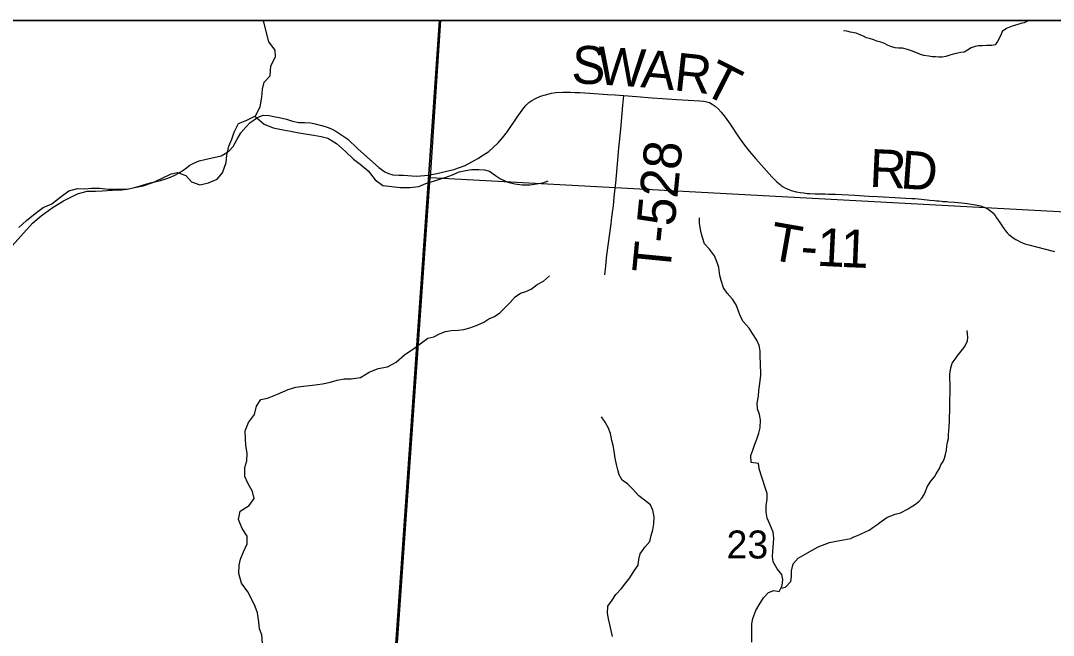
# Model space of a CAD drawing. Extents: x -8.2 to 34, y 0 to 22.
# Drawn here: x 6.05 to 7.595, y 19.98 to 20.9 of the extents above; entities that cross this region are included whole.
import ezdxf

# ---------------------------------------------------------------- set-up
doc = ezdxf.new("R2010")
doc.units = 0
for name, color, linetype in [('GM_X_Corporation', 7, 'Continuous'), ('GM_X_Minor_River', 7, 'Continuous'), ('GM_X_Section_Text', 7, 'Continuous'), ('GM_X_Township_Road', 7, 'Continuous'), ('GM_X_Township_Road_Text', 7, 'Continuous'), ('GM_X_Township_Text', 7, 'Continuous'), ('SH_Data', 7, 'Continuous')]:
    doc.layers.add(name, color=color, linetype=linetype)

msp = doc.modelspace()

# ---------------------------------------------------------------- linework, layer by layer
at = {"layer": 'GM_X_Corporation'}
msp.add_lwpolyline([(6.4774, 18.0203), (6.488, 18.1752), (6.5242, 18.7061), (6.5297, 18.7882), (6.5448, 18.981), (6.5455, 18.9878), (6.5461, 19.0017), (6.5463, 19.009), (6.5469, 19.0218), (6.548, 19.0467), (6.5487, 19.0617), (6.5495, 19.0821), (6.5503, 19.0966), (6.5514, 19.1092), (6.5523, 19.118), (6.5529, 19.1264), (6.5537, 19.1382), (6.5541, 19.1447), (6.5536, 19.1514), (6.5814, 19.5334), (6.6608, 20.6695), (6.6768, 20.9), (2.1, 20.9), (2.1, 14.1)], dxfattribs=at)
for points in [[(7.7078, 20.9), (6.6786, 20.9), (6.6629, 20.6653), (7.6877, 20.6096)], [(6.6629, 20.6653), (7.6877, 20.6096), (7.6147, 19.5864), (6.5914, 19.6487)]]:
    msp.add_lwpolyline(points, close=True, dxfattribs=at)
at = {"layer": 'GM_X_Minor_River'}
for points in [[(6.0474, 20.5902), (6.0587, 20.6008), (6.072, 20.6114), (6.0841, 20.6201), (6.097, 20.6258), (6.1106, 20.6368), (6.1223, 20.6452), (6.1352, 20.6486), (6.1458, 20.6482), (6.1564, 20.649), (6.1681, 20.649), (6.1814, 20.6479), (6.1958, 20.6475), (6.2094, 20.6479), (6.223, 20.6506), (6.2336, 20.6528), (6.248, 20.6578), (6.2609, 20.6635), (6.2753, 20.6707), (6.2851, 20.6726), (6.2972, 20.668), (6.3056, 20.6586), (6.3184, 20.6544), (6.3313, 20.6574), (6.3442, 20.6628), (6.3521, 20.6722), (6.3578, 20.6878), (6.3589, 20.6988), (6.3615, 20.7121), (6.3661, 20.7227), (6.3695, 20.7329), (6.3763, 20.7458), (6.3876, 20.7504), (6.4016, 20.7576), (6.4088, 20.7709), (6.4111, 20.7853), (6.4122, 20.7975), (6.4144, 20.8077), (6.4235, 20.8172), (6.4243, 20.8324), (6.4314, 20.846), (6.4311, 20.8559), (6.4216, 20.8684), (6.4174, 20.8836), (6.4147, 20.8961), (6.4129, 20.9)], [(7.5582, 20.9), (7.5577, 20.8997), (7.5516, 20.8967), (7.5467, 20.8955), (7.541, 20.8935), (7.5354, 20.8923), (7.5301, 20.8904), (7.5252, 20.8884), (7.5191, 20.8838), (7.5169, 20.8781), (7.5117, 20.8689), (7.5083, 20.8636), (7.5034, 20.8628), (7.4962, 20.8627), (7.489, 20.8622), (7.4837, 20.8622), (7.4784, 20.8614), (7.4727, 20.8594), (7.467, 20.8556), (7.4621, 20.8529), (7.4572, 20.8524), (7.4527, 20.8513), (7.4474, 20.8504), (7.4406, 20.8485), (7.4345, 20.8465), (7.4292, 20.8453), (7.4243, 20.8453), (7.419, 20.8456), (7.414, 20.846), (7.4091, 20.847), (7.4015, 20.8477), (7.3969, 20.8492), (7.3897, 20.8522), (7.3832, 20.8548), (7.3771, 20.857), (7.3699, 20.8588), (7.3638, 20.8588), (7.3588, 20.8591), (7.3539, 20.8606), (7.3482, 20.8628), (7.3428, 20.8658), (7.3375, 20.8677), (7.3314, 20.8695), (7.3268, 20.8714), (7.3204, 20.8732), (7.3158, 20.8743), (7.3112, 20.8769), (7.3051, 20.8791), (7.3002, 20.8814), (7.2918, 20.8828), (7.2865, 20.8843), (7.2815, 20.8846)], [(6.4008, 20.7572), (6.4145, 20.7451), (6.4282, 20.7394), (6.4429, 20.7368), (6.4539, 20.7345), (6.4638, 20.7326), (6.4789, 20.73), (6.4888, 20.7288), (6.5001, 20.7266), (6.51, 20.7239), (6.5228, 20.7163), (6.5365, 20.7042), (6.5482, 20.6928), (6.5581, 20.6852), (6.5702, 20.675), (6.5808, 20.6617), (6.5922, 20.653), (6.6055, 20.6515), (6.6183, 20.6504), (6.6327, 20.6504), (6.646, 20.6515), (6.6564, 20.6564)], [(6.6564, 20.6564), (6.6855, 20.665), (6.6965, 20.6693), (6.7064, 20.6735), (6.7162, 20.6758), (6.7246, 20.6774), (6.736, 20.6774), (6.7444, 20.6767), (6.752, 20.6745), (6.7608, 20.6681), (6.7684, 20.6632), (6.7791, 20.6583), (6.7897, 20.6557), (6.8008, 20.6542), (6.8122, 20.6543), (6.8221, 20.6555), (6.8316, 20.6574), (6.8395, 20.6601)], [(7.1443, 19.9696), (7.1441, 19.9969), (7.1456, 20.0049), (7.1505, 20.0171), (7.1554, 20.0255), (7.1618, 20.0358), (7.1694, 20.0438), (7.1773, 20.0472), (7.1853, 20.0454), (7.1898, 20.0545), (7.1909, 20.0632), (7.189, 20.0708), (7.1821, 20.0795), (7.1763, 20.0897), (7.1751, 20.0981), (7.1758, 20.1057), (7.1765, 20.1175), (7.1772, 20.1254), (7.176, 20.1342), (7.1714, 20.1463), (7.1672, 20.1554), (7.166, 20.1641), (7.1656, 20.1736), (7.1674, 20.1835), (7.167, 20.1922), (7.1639, 20.2024), (7.1608, 20.2119), (7.1577, 20.221), (7.1553, 20.2294), (7.1542, 20.2373), (7.1435, 20.2388), (7.1427, 20.249), (7.1457, 20.257), (7.1487, 20.2658), (7.1517, 20.2734), (7.1547, 20.2825), (7.1569, 20.2905), (7.1572, 20.3023), (7.156, 20.3106), (7.1529, 20.319), (7.1525, 20.3273), (7.1543, 20.3379), (7.155, 20.3463), (7.1565, 20.3566), (7.1576, 20.3691), (7.1575, 20.3877), (7.157, 20.3961), (7.1566, 20.4055), (7.1554, 20.4139), (7.1519, 20.4218), (7.1454, 20.4317), (7.1401, 20.4396), (7.1312, 20.4495), (7.1274, 20.457), (7.1243, 20.465), (7.1208, 20.4745), (7.1155, 20.4832), (7.1074, 20.4922), (7.1017, 20.5002), (7.0982, 20.5108), (7.0966, 20.5184), (7.0947, 20.5305), (7.0923, 20.5381), (7.0885, 20.5479), (7.0812, 20.5578), (7.0735, 20.5661), (7.0704, 20.5752), (7.0681, 20.5843), (7.0661, 20.5968), (7.0661, 20.6048)], [(6.6384, 20.4093), (6.6595, 20.4249), (6.6686, 20.4269), (6.677, 20.4311), (6.6861, 20.4349), (6.6944, 20.4361), (6.7051, 20.4365), (6.7131, 20.4377), (6.7222, 20.4401), (6.7332, 20.4439), (6.7434, 20.4485), (6.751, 20.4535), (6.759, 20.457), (6.7673, 20.4627), (6.7749, 20.4703), (6.7828, 20.4783), (6.7903, 20.4864), (6.7979, 20.4921), (6.8059, 20.4944), (6.8139, 20.4979), (6.8233, 20.5051), (6.8328, 20.5101), (6.8415, 20.5182)], [(7.4596, 20.4079), (7.463, 20.4124), (7.4671, 20.4208), (7.4674, 20.4258), (7.4665, 20.4364)], [(6.412, 19.9675), (6.4112, 19.9804), (6.4078, 19.9898), (6.4067, 20.0001), (6.4044, 20.0134), (6.4013, 20.0228), (6.3953, 20.0354), (6.3903, 20.0448), (6.3805, 20.0577), (6.3767, 20.0725), (6.3774, 20.0847), (6.3793, 20.0941), (6.3838, 20.1048), (6.3891, 20.1169), (6.3891, 20.1283), (6.3815, 20.14), (6.3762, 20.1533), (6.3788, 20.1658), (6.3921, 20.1742), (6.3996, 20.1848), (6.397, 20.1951), (6.3901, 20.2076), (6.3856, 20.2174), (6.3856, 20.2311), (6.3886, 20.241), (6.3893, 20.2527), (6.3871, 20.2641), (6.3867, 20.274), (6.3859, 20.2861), (6.3912, 20.2982), (6.3999, 20.3104), (6.4033, 20.3229), (6.4097, 20.3328), (6.4195, 20.335), (6.4343, 20.3407), (6.4506, 20.348), (6.4619, 20.3514), (6.4733, 20.3529), (6.4869, 20.3544), (6.5021, 20.3563), (6.5138, 20.359), (6.524, 20.3616), (6.5342, 20.3636), (6.5448, 20.3636), (6.5585, 20.3658), (6.5717, 20.3738), (6.585, 20.3795), (6.599, 20.3818), (6.6122, 20.389), (6.6247, 20.3996), (6.6384, 20.4093)], [(7.2924, 20.1247), (7.2971, 20.1274), (7.3024, 20.1293), (7.3069, 20.1313), (7.3156, 20.1352), (7.3201, 20.1375), (7.3254, 20.1413), (7.3314, 20.1452), (7.3359, 20.1487), (7.3461, 20.1564), (7.3525, 20.1587), (7.3586, 20.161), (7.3669, 20.1634), (7.3782, 20.1692), (7.3828, 20.1723), (7.3877, 20.175), (7.3941, 20.1804), (7.3989, 20.1854), (7.4023, 20.1907), (7.4041, 20.1953), (7.4067, 20.2021), (7.4123, 20.2106), (7.4176, 20.2171), (7.4202, 20.2217), (7.425, 20.2297), (7.4273, 20.235), (7.4306, 20.24), (7.4325, 20.2449), (7.4343, 20.2503), (7.4358, 20.2568), (7.4361, 20.2628), (7.4371, 20.2689), (7.4386, 20.2743), (7.4385, 20.2803), (7.4389, 20.2857), (7.4396, 20.2925), (7.4399, 20.3001), (7.4401, 20.3089), (7.4405, 20.3134), (7.4408, 20.3203), (7.4407, 20.3263), (7.4406, 20.3351), (7.441, 20.3397), (7.4409, 20.345), (7.4412, 20.3499), (7.4411, 20.3579), (7.4407, 20.3625), (7.4406, 20.3708), (7.4421, 20.3803), (7.4439, 20.3872), (7.4487, 20.3933), (7.4517, 20.3979), (7.4555, 20.4029), (7.4596, 20.4079)], [(6.9385, 20.2555), (6.9369, 20.2639), (6.9349, 20.2715), (6.9326, 20.2821), (6.9295, 20.2912), (6.9249, 20.2991), (6.9195, 20.3071)], [(6.9359, 19.9783), (6.9339, 19.9871), (6.9316, 19.9962), (6.93, 20.0045), (6.9281, 20.0129), (6.9288, 20.0235), (6.9352, 20.0326), (6.9408, 20.041), (6.9495, 20.0502), (6.956, 20.0582), (6.9616, 20.0658), (6.9684, 20.0765), (6.9741, 20.0849), (6.9751, 20.0932), (6.977, 20.102), (6.9842, 20.1119), (6.9917, 20.1203), (6.9939, 20.1294), (6.9962, 20.1378), (6.9976, 20.1469), (6.998, 20.1571), (6.9964, 20.167), (6.9929, 20.175), (6.9838, 20.1821), (6.975, 20.1889), (6.9658, 20.1991), (6.9585, 20.2067), (6.9505, 20.2123), (6.9459, 20.2199), (6.9436, 20.2278), (6.9416, 20.2358), (6.9397, 20.2449), (6.9385, 20.2555)], [(7.1878, 20.0504), (7.1948, 20.0519), (7.2027, 20.0603), (7.2038, 20.0679), (7.2038, 20.0762), (7.2064, 20.0869), (7.2135, 20.0953), (7.2241, 20.1014), (7.2355, 20.1079), (7.2435, 20.1121), (7.2605, 20.119), (7.2704, 20.1206), (7.2924, 20.1247)]]:
    msp.add_lwpolyline(points, dxfattribs=at)
at = {"layer": 'GM_X_Township_Road'}
for points in [[(6.661, 20.6689), (6.6772, 20.6724), (6.6856, 20.6742), (6.6985, 20.6774), (6.7071, 20.6801), (6.7152, 20.6834), (6.7255, 20.6886), (6.7342, 20.6937), (6.7429, 20.6991), (6.7506, 20.7042), (6.7579, 20.7107), (6.7648, 20.7173), (6.7713, 20.7247), (6.7785, 20.7341), (6.793, 20.7555), (6.803, 20.7695), (6.8066, 20.7737), (6.8106, 20.7774), (6.815, 20.7805), (6.8204, 20.7834), (6.8283, 20.7868), (6.8353, 20.7891), (6.8443, 20.7913), (6.8509, 20.7922), (6.8614, 20.7928), (6.8731, 20.7928), (6.8799, 20.7925), (6.8867, 20.7922), (6.9021, 20.7913), (6.9284, 20.7896), (6.9398, 20.789), (6.9528, 20.7878), (6.9718, 20.7866), (6.9953, 20.7846), (7.0107, 20.7833), (7.0318, 20.7819), (7.0666, 20.7801), (7.0721, 20.7796), (7.0768, 20.7787), (7.0808, 20.7774), (7.0851, 20.7752), (7.0895, 20.772), (7.0941, 20.768), (7.0986, 20.763), (7.1042, 20.7556), (7.1117, 20.745), (7.1255, 20.7244), (7.1331, 20.7137), (7.1409, 20.7039), (7.1503, 20.6931), (7.1665, 20.6752), (7.1742, 20.6663), (7.1782, 20.6622), (7.1819, 20.6589), (7.1867, 20.6546), (7.1884, 20.6531), (7.1911, 20.6514), (7.1947, 20.6493), (7.1988, 20.6475), (7.2034, 20.6458), (7.2106, 20.6439), (7.2171, 20.6426), (7.2222, 20.642), (7.2272, 20.6414), (7.2309, 20.6412), (7.239, 20.6408), (7.247, 20.6405), (7.2538, 20.6405), (7.2592, 20.6403), (7.2623, 20.6402), (7.2697, 20.64), (7.279, 20.6396), (7.2982, 20.6387), (7.3193, 20.6374), (7.3323, 20.6368), (7.367, 20.6349), (7.3744, 20.6345), (7.3836, 20.6339), (7.3884, 20.6336), (7.398, 20.6328), (7.4109, 20.6315), (7.4175, 20.6308), (7.4211, 20.6304), (7.4241, 20.6301), (7.4282, 20.6297), (7.43, 20.6295), (7.4355, 20.6291), (7.4391, 20.6288), (7.4475, 20.6281), (7.4587, 20.6271), (7.4663, 20.6262), (7.4791, 20.6243), (7.4863, 20.6226), (7.4921, 20.6207), (7.498, 20.6178), (7.5015, 20.6155), (7.5051, 20.6122), (7.5082, 20.6085), (7.5106, 20.6049), (7.5153, 20.5979), (7.5163, 20.5963), (7.52, 20.5908), (7.5218, 20.5883), (7.5225, 20.5873), (7.524, 20.5853), (7.5265, 20.5826), (7.5291, 20.5799), (7.531, 20.5782), (7.5329, 20.5767), (7.5355, 20.5748), (7.5392, 20.5725), (7.5423, 20.5707), (7.5457, 20.569), (7.5526, 20.5661), (7.5586, 20.5642), (7.5701, 20.5614), (7.5839, 20.5579), (7.5972, 20.5546)], [(6.9244, 20.5194), (6.9256, 20.5324), (6.9269, 20.5448), (6.9288, 20.5601), (6.9317, 20.5816), (6.9336, 20.5958), (6.9349, 20.6056), (6.9358, 20.613), (6.9371, 20.6228), (6.9385, 20.6357), (6.94, 20.6491), (6.9407, 20.6565), (6.9418, 20.6683), (6.9453, 20.7091), (6.9482, 20.7376), (6.9514, 20.7728), (6.9528, 20.7878)], [(6.0328, 20.5581), (6.068, 20.5966), (6.0807, 20.6076), (6.0971, 20.6198), (6.1145, 20.6304), (6.1354, 20.6405), (6.1497, 20.6445), (6.1623, 20.6449), (6.1723, 20.6451), (6.1876, 20.6461), (6.2013, 20.6466), (6.2094, 20.6476), (6.2204, 20.6503), (6.2309, 20.653), (6.2388, 20.6557), (6.2467, 20.6576), (6.2594, 20.6609), (6.2674, 20.6634), (6.2745, 20.6658), (6.2821, 20.669), (6.2888, 20.6731), (6.2964, 20.6781), (6.3035, 20.6835), (6.3105, 20.687), (6.3174, 20.6903), (6.3257, 20.692), (6.3325, 20.6936), (6.3435, 20.6961), (6.3503, 20.6978), (6.3562, 20.7009), (6.3622, 20.7052), (6.368, 20.7115), (6.3744, 20.7224), (6.3798, 20.7322), (6.387, 20.7407), (6.3935, 20.7473), (6.3995, 20.7517), (6.4047, 20.755), (6.4131, 20.7585), (6.4218, 20.7579), (6.4289, 20.7564), (6.4372, 20.755), (6.4478, 20.7523), (6.4571, 20.7496), (6.4664, 20.7477), (6.4749, 20.7475), (6.484, 20.7469), (6.4909, 20.7457), (6.5025, 20.7425), (6.5089, 20.7407), (6.5153, 20.738), (6.5218, 20.7344), (6.54, 20.7226), (6.5543, 20.7088), (6.5862, 20.6801), (6.5953, 20.6739), (6.6007, 20.6714), (6.6072, 20.6692), (6.6159, 20.6687), (6.6231, 20.6685), (6.6418, 20.6671), (6.661, 20.6689)]]:
    msp.add_lwpolyline(points, dxfattribs=at)
at = {"layer": 'GM_X_Township_Text'}
msp.add_lwpolyline([(6.6768, 20.9), (6.6608, 20.6695), (6.5814, 19.5334), (6.5536, 19.1514), (6.5541, 19.1447), (6.5537, 19.1382), (6.5529, 19.1264), (6.5523, 19.118), (6.5514, 19.1092), (6.5503, 19.0966), (6.5495, 19.0821), (6.5487, 19.0617), (6.548, 19.0467), (6.5469, 19.0218), (6.5463, 19.009), (6.5461, 19.0017), (6.5455, 18.9878), (6.5448, 18.981), (6.5297, 18.7882), (6.5242, 18.7061), (6.488, 18.1752), (6.4774, 18.0203)], dxfattribs=at)
at = {"layer": 'SH_Data'}
msp.add_line((2.1, 20.9), (8.9, 20.9), dxfattribs=at)

# ---------------------------------------------------------------- texts
at = {"layer": 'GM_X_Section_Text'}
msp.add_text('23', height=0.04186, rotation=0, dxfattribs=at).set_placement((7.1065, 20.0949))
at = {"layer": 'GM_X_Township_Road_Text'}
for s, height, rotation, p in [('S', 0.0568, 357.4667, (6.8737, 20.8064)), ('W', 0.0568, 356.3262, (6.9117, 20.8047)), ('A', 0.0568, 354.7396, (6.977, 20.8005)), ('R', 0.0568, 353.8094, (7.0265, 20.7959)), ('T', 0.0568, 333.0555, (7.0677, 20.7924)), ('T-528', 0.05682, 84.4613, (7.0217, 20.5196)), ('R', 0.0568, 357.3724, (7.3195, 20.6513)), ('D', 0.0568, 355.8254, (7.3657, 20.6492)), ('T', 0.0568, 350.1114, (7.1679, 20.543)), ('1', 0.0568, 357.1865, (7.2407, 20.5332)), ('1', 0.0568, 357.7129, (7.2762, 20.5314)), ('-', 0.0568, 355.939, (7.2161, 20.5349))]:
    msp.add_text(s, height=height, rotation=rotation, dxfattribs=at).set_placement(p)

doc.saveas('drawing.dxf')
